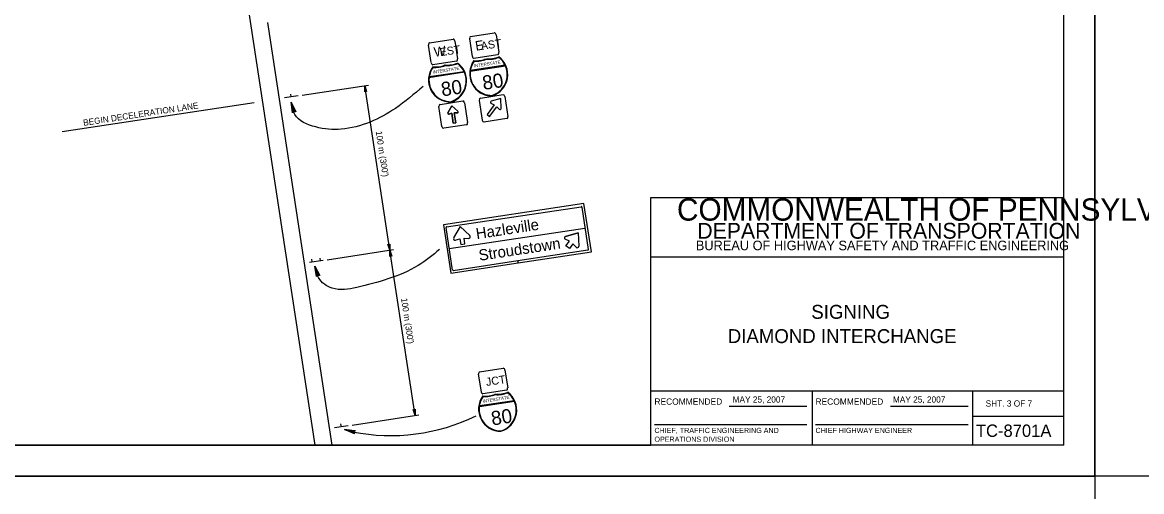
# Model space of a CAD drawing. Extents: x 640994 to 644422, y 298458 to 299646.
# Drawn here: x 642998 to 643540, y 299044 to 299271 of the extents above; entities that cross this region are included whole.
import ezdxf

# ---------------------------------------------------------------- set-up
doc = ezdxf.new("R2010")
doc.units = 0
for name, color, linetype in [('1', 7, 'Continuous'), ('2', 7, 'Continuous'), ('XCS-GRID-MIN', 7, 'Continuous')]:
    doc.layers.add(name, color=color, linetype=linetype)

msp = doc.modelspace()

# ---------------------------------------------------------------- linework, layer by layer
at = {"layer": '1'}
for p, q in [((643502.31, 299066.63), (643502.31, 299630.63)), ((643302.31, 299066.63), (643302.31, 299186.63)), ((643302.31, 299186.63), (643502.31, 299186.63)), ((643502.31, 299157.63), (643302.31, 299157.63)), ((643302.31, 299093), (643502.31, 299093)), ((643380.31, 299093), (643380.31, 299066.63)), ((643458.19, 299066.63), (643458.19, 299093)), ((643340.24, 299085.57), (643377.87, 299085.57)), ((643418.24, 299085.57), (643455.87, 299085.57)), ((643458.19, 299080.63), (643502.31, 299080.63)), ((643303.99, 299076.68), (643377.87, 299076.68)), ((643381.99, 299076.68), (643455.87, 299076.68)), ((643502.31, 299066.63), (642716.31, 299066.63)), ((642716.31, 299066.63), (643302.31, 299066.63))]:
    msp.add_line(p, q, dxfattribs=at)
at = {"layer": '2'}
for p, q in [((643102.81, 299307.63), (643139.56, 299066.63)), ((643116.56, 299271.38), (643147.69, 299066.63)), ((643195.06, 299261.5), (643206.56, 299263.25)), ((643207.31, 299262.25), (643208.69, 299253.75)), ((643215.81, 299254.88), (643214.56, 299263.38)), ((643214.94, 299264.5), (643226.44, 299266.25)), ((643227.31, 299265.38), (643228.56, 299256.88)), ((643195.94, 299251.88), (643194.56, 299260.38)), ((643201.56, 299257.13), (643201.56, 299257.13)), ((643221.56, 299260.13), (643221.56, 299260.13)), ((643208.19, 299252.63), (643196.69, 299250.88)), ((643208.69, 299251.38), (643208.69, 299251.38)), ((643228.06, 299255.63), (643216.56, 299253.88)), ((643216.69, 299252.63), (643216.69, 299252.63)), ((643222.56, 299253.63), (643222.56, 299253.63)), ((643228.56, 299254.5), (643228.56, 299254.5)), ((643194.81, 299244.75), (643211.94, 299247.38)), ((643211.81, 299247.5), (643194.94, 299245)), ((643196.81, 299249.63), (643196.81, 299249.63)), ((643202.69, 299250.5), (643202.69, 299250.5)), ((643231.69, 299250.63), (643214.81, 299248)), ((643214.81, 299247.75), (643231.81, 299250.38)), ((643133.31, 299236.13), (643165.56, 299241)), ((643175.81, 299161), (643163.69, 299240.75)), ((643204.06, 299241.75), (643204.06, 299241.75)), ((643223.94, 299244.75), (643223.94, 299244.75)), ((643131.44, 299235.88), (643124.81, 299234.88)), ((643128.06, 299235.38), (643127.94, 299236.63)), ((643219.69, 299234.63), (643230.69, 299236.38)), ((643231.56, 299235.5), (643233.06, 299225.88)), ((643017.19, 299218.5), (643110.06, 299232.63)), ((643122.19, 299234.38), (643122.19, 299234.38)), ((643201.06, 299221), (643199.56, 299230.63)), ((643200.19, 299231.63), (643211.19, 299233.38)), ((643203.94, 299227.63), (643205.94, 299231)), ((643205.94, 299231), (643203.94, 299227.63)), ((643205.94, 299231), (643208.81, 299228.38)), ((643208.81, 299228.38), (643205.94, 299231)), ((643212.06, 299232.5), (643213.44, 299222.88)), ((643220.69, 299224), (643219.19, 299233.63)), ((643226.31, 299231.5), (643222.94, 299226.75)), ((643224.19, 299225.75), (643227.69, 299230.5)), ((643224.81, 299232.25), (643226.31, 299231.5)), ((643229.56, 299234.5), (643224.94, 299233.25)), ((643226.06, 299229.75), (643226.06, 299229.75)), ((643227.69, 299230.5), (643228.81, 299229.38)), ((643229.69, 299229.75), (643229.56, 299234.5)), ((643205.81, 299227.38), (643204.44, 299226.88)), ((643204.44, 299226.88), (643205.81, 299227.38)), ((643206.56, 299222.5), (643205.81, 299227.38)), ((643205.81, 299227.38), (643206.56, 299222.5)), ((643208.44, 299227.5), (643207.06, 299227.5)), ((643207.06, 299227.5), (643207.81, 299222.75)), ((643207.81, 299222.75), (643207.06, 299227.5)), ((643207.06, 299227.5), (643208.44, 299227.5)), ((643232.44, 299224.88), (643221.44, 299223.13)), ((643222.94, 299226.75), (643224.19, 299225.75)), ((643212.94, 299221.75), (643201.94, 299220.13)), ((643207.81, 299222.75), (643206.56, 299222.5)), ((643206.56, 299222.5), (643207.81, 299222.75)), ((643269.81, 299183.63), (643201.81, 299173.38)), ((643203.31, 299172.38), (643268.44, 299182.13)), ((643268.81, 299181.88), (643271.94, 299161.38)), ((643273.44, 299160.25), (643269.81, 299183.63)), ((643201.81, 299173.38), (643205.44, 299150)), ((643206.19, 299151.38), (643203.06, 299172)), ((643204.56, 299161.88), (643270.31, 299171.75)), ((643209.94, 299172.5), (643206.69, 299167)), ((643209.94, 299172.5), (643206.69, 299167)), ((643214.56, 299168.13), (643209.94, 299172.5)), ((643214.56, 299168.13), (643209.94, 299172.5)), ((643207.56, 299165.88), (643209.69, 299166.5)), ((643207.56, 299165.88), (643209.69, 299166.5)), ((643209.69, 299166.5), (643210.19, 299163.75)), ((643209.69, 299166.5), (643210.19, 299163.75)), ((643212.19, 299164.13), (643211.81, 299166.88)), ((643211.81, 299166.88), (643214.06, 299166.75)), ((643212.19, 299164.13), (643211.81, 299166.88)), ((643211.81, 299166.88), (643214.06, 299166.75)), ((643237.56, 299166.75), (643237.56, 299166.75)), ((643262.81, 299165.38), (643260.81, 299166.38)), ((643262.81, 299165.38), (643260.81, 299166.38)), ((643260.94, 299167.75), (643267.06, 299169.38)), ((643260.94, 299167.75), (643267.06, 299169.38)), ((643267.06, 299169.38), (643260.94, 299167.75)), ((643260.94, 299167.75), (643267.06, 299169.38)), ((643260.94, 299167.75), (643267.06, 299169.38)), ((643267.06, 299169.38), (643260.94, 299167.75)), ((643261.06, 299163.13), (643262.81, 299165.38)), ((643261.06, 299163.13), (643262.81, 299165.38)), ((643267.06, 299169.38), (643267.31, 299163)), ((643267.06, 299169.38), (643267.31, 299163)), ((643145.44, 299156.38), (643177.69, 299161.38)), ((643188.06, 299081), (643175.81, 299161)), ((643210.19, 299163.75), (643212.19, 299164.13)), ((643210.19, 299163.75), (643212.19, 299164.13)), ((643271.69, 299161), (643237.87, 299155.87)), ((643238.02, 299154.91), (643273.44, 299160.25)), ((643262.81, 299161.88), (643261.06, 299163.13)), ((643262.81, 299161.88), (643261.06, 299163.13)), ((643264.44, 299164.13), (643262.81, 299161.88)), ((643264.44, 299164.13), (643262.81, 299161.88)), ((643266.06, 299162.5), (643264.44, 299164.13)), ((643266.06, 299162.5), (643264.44, 299164.13)), ((643266.06, 299162.5), (643266.06, 299162.5)), ((643134.31, 299154.75), (643134.31, 299154.75)), ((643143.56, 299156.13), (643136.94, 299155.13)), ((643138.19, 299155.38), (643138.06, 299156.63)), ((643142.19, 299155.88), (643142.06, 299157.25)), ((643205.44, 299150), (643238.02, 299154.91)), ((643237.87, 299155.87), (643206.56, 299151.13)), ((643237.87, 299155.87), (643238.02, 299154.91)), ((643238.02, 299154.91), (643237.87, 299155.87)), ((643220.19, 299092.5), (643218.81, 299101)), ((643219.31, 299102.13), (643230.81, 299103.88)), ((643231.56, 299102.88), (643232.94, 299094.38)), ((643225.81, 299097.63), (643225.81, 299097.63)), ((643232.44, 299093.25), (643220.94, 299091.5)), ((643221.06, 299090.25), (643221.06, 299090.25)), ((643226.94, 299091.13), (643226.94, 299091.13)), ((643232.94, 299092), (643232.94, 299092)), ((643236.06, 299088.13), (643219.19, 299085.63)), ((643219.19, 299085.38), (643236.19, 299087.88)), ((643157.56, 299076.38), (643189.94, 299081.25)), ((643146.44, 299075), (643146.44, 299075)), ((643146.44, 299074.63), (643146.44, 299074.63)), ((643155.69, 299076), (643149.06, 299075)), ((643152.44, 299075.5), (643152.19, 299076.88))]:
    msp.add_line(p, q, dxfattribs=at)
for points in [[(643163.76, 299237.88), (643163.95, 299238.01), (643163.69, 299240.75), (643163.76, 299237.88), (643163.66, 299237.71), (643163.69, 299240.75), (643164.23, 299238.06), (643164.45, 299237.99), (643163.69, 299240.75), (643164.61, 299237.86), (643164.45, 299237.99)], [(643128.81, 299227.88), (643129.06, 299228.13), (643128.06, 299232.75), (643128.81, 299227.88), (643128.69, 299227.5), (643128.06, 299232.75), (643129.56, 299228.25), (643129.94, 299228.25), (643128.06, 299232.75), (643130.31, 299228), (643129.94, 299228.25)], [(643175.74, 299163.88), (643175.55, 299163.74), (643175.81, 299161), (643175.74, 299163.88), (643175.84, 299164.04), (643175.81, 299161), (643175.27, 299163.7), (643175.05, 299163.76), (643175.81, 299161), (643174.89, 299163.9), (643175.05, 299163.76)], [(643175.89, 299158.13), (643176.08, 299158.26), (643175.81, 299161), (643175.89, 299158.13), (643175.79, 299157.96), (643175.81, 299161), (643176.36, 299158.31), (643176.58, 299158.24), (643175.81, 299161), (643176.74, 299158.11), (643176.58, 299158.24)], [(643140.44, 299148.5), (643140.81, 299148.75), (643139.56, 299153.38), (643140.44, 299148.5), (643140.31, 299148.25), (643139.56, 299153.38), (643141.19, 299149), (643141.56, 299148.88), (643139.56, 299153.38), (643141.94, 299148.75), (643141.56, 299148.88)], [(643187.98, 299083.88), (643187.8, 299083.74), (643188.06, 299081), (643187.98, 299083.88), (643188.09, 299084.04), (643188.06, 299081), (643187.51, 299083.69), (643187.3, 299083.76), (643188.06, 299081), (643187.14, 299083.89), (643187.3, 299083.76)], [(643158.51, 299072.37), (643158.39, 299072.74), (643153.96, 299074.16), (643158.51, 299072.37), (643158.73, 299072.06), (643153.96, 299074.16), (643158.54, 299073.16), (643158.77, 299073.49), (643153.96, 299074.16), (643159.15, 299073.61), (643158.77, 299073.49)]]:
    msp.add_lwpolyline(points, dxfattribs=at)
for centre, radius, start, end in [((643203.86, 299263.04), 12.33, 264.4038, 292.9038), ((643203.86, 299263.04), 12.56, 264.6648, 292.3133), ((643202.3, 299243.04), 10.73, 286.7839, 53.6538), ((643202.3, 299243.04), 10.51, 25.4466, 52.9614), ((643225.23, 299246.52), 10.73, 143.6538, 270.5237), ((643225.23, 299246.52), 10.51, 144.3462, 171.8611), ((643217.79, 299265.16), 12.33, 264.4038, 292.9038), ((643217.79, 299265.16), 12.56, 264.9943, 292.6428), ((643223.79, 299266.07), 12.33, 264.4038, 292.9038), ((643223.79, 299266.07), 12.56, 264.6648, 292.3133), ((643222.23, 299246.07), 10.73, 286.7839, 53.6538), ((643222.23, 299246.07), 10.51, 25.4466, 52.9614), ((643205.3, 299243.49), 10.73, 143.6538, 270.5237), ((643205.3, 299243.49), 10.51, 144.3462, 171.8611), ((643197.86, 299262.12), 12.33, 264.4038, 292.9038), ((643197.86, 299262.12), 12.56, 264.9943, 292.6428), ((643202.3, 299243.04), 10.51, 286.7839, 24.1669), ((643225.23, 299246.52), 10.51, 173.1407, 270.5237), ((643222.23, 299246.07), 10.51, 286.7839, 24.1669), ((643205.3, 299243.49), 10.51, 173.1407, 270.5237), ((643225.07, 299232.74), 0.5, 103.9183, 245.5492), ((643229.19, 299229.7), 0.5, 225, 1.3737), ((643204.37, 299227.38), 0.46, 148.5129, 289.1785), ((643204.37, 299227.38), 0.46, 148.5129, 289.1785), ((643208.49, 299227.98), 0.46, 266.9014, 50.808), ((643208.49, 299227.98), 0.46, 266.9014, 50.8081), ((643268.53, 299181.93), 0.309, 7.3907, 98.4613), ((643203.39, 299172.11), 0.309, 98.9487, 188.5961), ((643207.4, 299166.56), 0.745, 148.5129, 289.1785), ((643207.4, 299166.56), 0.745, 148.5129, 289.1785), ((643214.08, 299167.54), 0.745, 266.9014, 50.8081), ((643214.08, 299167.54), 0.745, 266.9014, 50.8081), ((643261.15, 299167), 0.745, 103.5129, 244.1785), ((643261.15, 299167), 0.745, 103.5129, 244.1785), ((643266.57, 299162.97), 0.745, 221.9014, 5.8081), ((643266.57, 299162.97), 0.745, 221.9014, 5.8081), ((643271.71, 299161.4), 0.309, 278.3685, 10.1781), ((643206.58, 299151.55), 0.309, 189.1727, 276.4437), ((643229.56, 299084.08), 10.73, 143.6538, 270.5237), ((643229.56, 299084.08), 10.51, 144.3462, 171.8611), ((643222.12, 299102.71), 12.33, 264.4038, 292.9038), ((643222.12, 299102.71), 12.56, 264.9943, 292.6428), ((643228.12, 299103.62), 12.33, 264.4038, 292.9038), ((643228.12, 299103.62), 12.56, 264.6648, 292.3133), ((643226.56, 299083.62), 10.73, 286.7839, 53.6538), ((643226.56, 299083.62), 10.51, 25.4466, 52.9614), ((643229.56, 299084.08), 10.51, 173.1407, 270.5237), ((643226.56, 299083.62), 10.51, 286.7839, 24.1669), ((643176.31, 299165.19), 93.92, 258.636, 296.1278)]:
    msp.add_arc(centre, radius, start, end, dxfattribs=at)
for centre, major_axis, ratio, start_param, end_param in [((643206.7, 299262.21), (-0.16, 1.06), 0.6, 4.712389, 6.283185), ((643215.15, 299263.5), (0.16, -1.06), 0.6, 3.141593, 4.712389), ((643226.63, 299265.25), (-0.16, 1.06), 0.6, 4.712389, 6.283185), ((643195.22, 299260.47), (0.16, -1.06), 0.6, 3.141593, 4.712389), ((643227.92, 299256.74), (-0.16, 1.06), 0.6, 3.141593, 4.712389), ((643196.51, 299251.96), (0.16, -1.06), 0.6, 4.712389, 6.283185), ((643207.99, 299253.71), (-0.16, 1.06), 0.6, 3.141593, 4.712389), ((643216.44, 299255), (0.16, -1.06), 0.6, 4.712389, 6.283185), ((643230.85, 299235.42), (-0.14, 0.921), 0.769266, 4.712389, 6.283185), ((643200.32, 299230.73), (0.14, -0.921), 0.769266, 3.141593, 4.712389), ((643211.3, 299232.4), (-0.14, 0.921), 0.769266, 4.712389, 6.283185), ((643219.86, 299233.75), (0.14, -0.921), 0.769266, 3.141593, 4.712389), ((643232.32, 299225.75), (-0.14, 0.921), 0.769266, 3.141593, 4.712389), ((643201.79, 299221.06), (0.14, -0.921), 0.769266, 4.712389, 6.283185), ((643212.78, 299222.73), (-0.14, 0.921), 0.769266, 3.141593, 4.712389), ((643221.33, 299224.08), (0.14, -0.921), 0.769266, 4.712389, 6.283185), ((643219.48, 299101.05), (0.16, -1.06), 0.6, 3.141593, 4.712389), ((643230.96, 299102.8), (-0.16, 1.06), 0.6, 4.712389, 6.283185), ((643232.25, 299094.3), (-0.16, 1.06), 0.6, 3.141593, 4.712389), ((643220.78, 299092.55), (0.16, -1.06), 0.6, 4.712389, 6.283185)]:
    msp.add_ellipse(centre, major_axis=major_axis, ratio=ratio, start_param=start_param, end_param=end_param, dxfattribs=at)
for points in [[(643191.94, 299240.38), (643178.56, 299229.75), (643166.31, 299223.13), (643152.31, 299219.63), (643139.94, 299220.75), (643129.81, 299226.75), (643128.06, 299232.75)], [(643199.94, 299161.38), (643189.56, 299153.63), (643174.94, 299147.13), (643159.81, 299143), (643147.94, 299142.63), (643141.31, 299147.75), (643139.56, 299153.38)]]:
    msp.add_spline(points, degree=3, dxfattribs=at)
at = {"layer": 'XCS-GRID-MIN'}
for points in [[(642676.31, 299645.63), (643517.31, 299645.63), (643517.31, 299051.63), (642676.31, 299051.63)], [(643517.31, 299645.63), (644358.31, 299645.63), (644358.31, 299051.63), (643517.31, 299051.63)], [(642676.31, 299051.63), (643517.31, 299051.63), (643517.31, 298457.63), (642676.31, 298457.63)]]:
    msp.add_lwpolyline(points, close=True, dxfattribs=at)

# ---------------------------------------------------------------- texts
at = {"layer": '1'}
for s, height, p in [('COMMONWEALTH OF PENNSYLVANIA', 10.7828, (643314.9, 299175.36)), ('DEPARTMENT OF TRANSPORTATION', 7.6837, (643324.76, 299166.61)), ('BUREAU OF HIGHWAY SAFETY AND TRAFFIC ENGINEERING', 4.6253, (643324.04, 299161.04)), ('SIGNING', 6.75, (643379.96, 299127.81)), ('DIAMOND INTERCHANGE', 6.75, (643339.49, 299116.06)), ('RECOMMENDED', 3.048, (643303.99, 299086.2)), ('RECOMMENDED', 3.048, (643381.99, 299086.2)), ('SHT. 3 OF 7', 3, (643464.4, 299085.31)), ('CHIEF, TRAFFIC ENGINEERING AND', 2.5, (643303.99, 299072.51)), ('CHIEF HIGHWAY ENGINEER', 2.5, (643381.99, 299072.51)), ('TC-8701A', 6, (643459.68, 299070.63)), ('OPERATIONS DIVISION', 2.5, (643303.99, 299068.26))]:
    msp.add_text(s, height=height, dxfattribs=at).set_placement(p)
at = {"layer": '2'}
for s, height, rotation, p in [('E', 4.63, 8.6525, (643217.56, 299257.63)), ('AST', 3.875, 8.6538, (643220.19, 299258)), ('W', 4.63, 8.6525, (643197.56, 299254.63)), ('EST', 3.875, 8.6538, (643200.31, 299255)), ('INTERSTATE', 1.517, 8.6538, (643216.69, 299249.5)), ('INTERSTATE', 1.517, 8.6538, (643196.69, 299246.5)), ('80', 6.829, 8.6538, (643221.19, 299238.63)), ('80', 6.829, 8.6538, (643201.19, 299235.5)), ('BEGIN DECELERATION LANE', 3, 8.6534, (643027.56, 299221.25)), ("100 m (300')", 3, 278.6536, (643169.01, 299218.53)), ('Hazleville  ', 5.3752, 8.6538, (643217.94, 299166.38)), ('Stroudstown', 5.3752, 8.6538, (643219.31, 299155.88)), ("100 m (300')", 3, 278.6537, (643181.26, 299137.65)), ('JCT', 3.896, 8.6538, (643222.69, 299095.25)), ('INTERSTATE', 1.517, 8.6538, (643220.94, 299087.13)), ('MAY 25, 2007', 3, 360, (643419.47, 299087.24)), ('80', 6.829, 8.6538, (643225.44, 299076.13))]:
    msp.add_text(s, height=height, rotation=rotation, dxfattribs=at).set_placement(p)
msp.add_text('MAY 25, 2007', height=3, dxfattribs=at).set_placement((643341.85, 299087.24))

doc.saveas('drawing.dxf')
